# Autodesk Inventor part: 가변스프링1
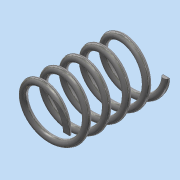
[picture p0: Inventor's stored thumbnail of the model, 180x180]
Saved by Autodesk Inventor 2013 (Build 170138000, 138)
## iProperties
Created: 2018-10
Part Number: 가변스프링1
Material: 스테인리스강
Document SubType Name: Modeling
Designer: Administrator
Density: 8.08 g/cm^3
Mass: 6.30638 g
Surface Area: 15.7949 cm^2
Volume: 0.780493 cm^3
Author: Administrator
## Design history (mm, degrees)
sketch "스케치1"
  geometry: L1 (0, 0)-(0, 30.255); L2 (0, 30.255)-(8, 30.255); L3 (0, 0)-(8, 0); C1 r 1 at (8, 0)
  constraints: 6 end point, 1 centre point, 1 coincident, 1 parallel, 1 perpendicular, 1 vertical
  dimensions: "d0" = 30.25501 distance of L1.start L1.end (derived); "d1" = 8 distance of L1.end L2.end; "d3" = 2 diameter of C1; "d4" = 16 diameter of L3.end L1
feature "코일1" sketch "스케치1" pitch "d5" = 10; turns "d7" = 5; dims "d6" = 30.25501 (= d0), "d8" = 0, angle "d9" = 90 deg, angle "d10" = 90 deg, "d11" = 0, "d12" = 0
sketch "스케치2"
  geometry: L1 (30.255, 10)-(0, 10); L2 (0, 10)-(0, -10); L3 (0, -10)-(30.255, -10); L4 (30.255, -10)-(30.255, 10); 2 further points
  constraints: 8 end point, 2 parallel, 1 coincident, 1 horizontal, 1 midpoint, 1 perpendicular
  dimensions: "d13" = 30.25501 distance of L2.end L3.end (derived); "d15" = 20 distance between parallel lines of L3 L1
extrude "돌출1" sketch "스케치2" stored distance "d16" = 0; taper "d17" = 0 deg
node "솔리드1"
